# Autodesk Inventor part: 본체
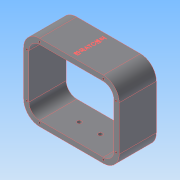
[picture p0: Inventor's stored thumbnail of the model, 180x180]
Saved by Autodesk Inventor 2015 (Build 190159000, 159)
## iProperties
Created: 2016-12
Part Number: 본체
Material: 알루미늄 6061
Document SubType Name: Modeling
Designer: mduedu
Density: 2.71 g/cm^3
Mass: 1066.02 g
Surface Area: 923.723 cm^2
Volume: 393.366 cm^3
Appearance: 기본값
Author: mduedu
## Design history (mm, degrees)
sketch "스케치1"
  geometry: L1 (-60, 72)-(60, 72); L2 (90, 42)-(90, -42); L3 (60, -72)-(-60, -72); L4 (-90, -42)-(-90, 42); A1 r 30 centre (-60, 42) between (-60, 72) and (-90, 42); A2 r 30 centre (60, 42) between (90, 42) and (60, 72); A3 r 30 centre (60, -42) between (60, -72) and (90, -42); A4 r 30 centre (-60, -42) between (-90, -42) and (-60, -72); 1 further point
  constraints: 8 end point, 8 point on circle, 8 tangent, 4 centre point, 3 equal radius, 2 parallel, 1 horizontal, 1 perpendicular
  dimensions: "d106" = 30 radius of A1; "d107" = 72 distance from line of L1 point (0, 0); "d108" = 144 distance between parallel lines of L3 L1; "d109" = 90 distance from line of L4 point (0, 0); "d110" = 180 distance between parallel lines of L2 L4
extrude "돌출1" new body sketch "스케치1" stored distance "d3" = 70; taper "d4" = 0 deg
feature "쉘1" dims "d5" = 10
sketch "스케치10"
  geometry: L1 (-30, 0)-(-30, 70) reference; 3 further points
  constraints: 2 coincident, 1 other
  dimensions: "d111" = 90 distance from line of point (60, 35) L1
feature "엠보싱1" sketch "스케치10" dims "d61" = 0.5, "d62" = 0, "d106" = 30, "d107" = 72, "d108" = 144, "d109" = 90, "d110" = 180
sketch "스케치16"
  geometry: L1 (-60, 62)-(60, 62) reference; L2 (80, 42)-(80, -42) reference; L3 (60, -62)-(-60, -62) reference; L4 (-80, -42)-(-80, 42) reference; L5 (60, 72)-(-60, 72) reference; L6 (-90, 42)-(-90, -42) reference; L7 (-60, -72)-(60, -72) reference; L8 (90, -42)-(90, 42) reference; L9 (60, 66)-(-60, 66); L10 (-84, 42)-(-84, -42); L11 (-60, -66)-(60, -66); L12 (84, -42)-(84, 42); A1 r 20 centre (60, 42) between (80, 42) and (60, 62) reference; A2 r 20 centre (60, -42) between (60, -62) and (80, -42) reference; A3 r 20 centre (-60, -42) between (-80, -42) and (-60, -62) reference; A4 r 20 centre (-60, 42) between (-60, 62) and (-80, 42) reference; A5 r 30 centre (-60, 42) between (-60, 72) and (-90, 42) reference; A6 r 30 centre (-60, -42) between (-90, -42) and (-60, -72) reference; A7 r 30 centre (60, -42) between (60, -72) and (90, -42) reference; A8 r 30 centre (60, 42) between (90, 42) and (60, 72) reference; A9 r 24 centre (-60, 42) between (-60, 66) and (-84, 42); A10 r 24 centre (-60, -42) between (-84, -42) and (-60, -66); A11 r 24 centre (60, -42) between (60, -66) and (84, -42); A12 r 24 centre (60, 42) between (84, 42) and (60, 66); 9 further points
  constraints: 8 coincident, 8 end point, 8 point on circle, 4 centre point, 7 other
  dimensions: "d124" = 6 distance between parallel lines of L9 L5
hole "구멍6" sketch "스케치16" at (-60, 66), (-84, 42), (-84, -42), (-60, -66), (60, -66), (84, -42), (84, 42), (60, 66) diameter "d113" = 3.242; stored, may be unused: countersink angle "d117" = 90 deg, drill point angle "d119" = 118 deg; dims "d114" = 7, "d115" = 4, "d116" = 2, "d118" = 9
sketch "스케치15"
  geometry: L1 (0, -70)-(0, 0) reference; L2 (-22.361, 0)-(0, 0) reference; L3 (-22.361, -70)-(-22.361, 0) reference; L4 (0, -70)-(-22.361, -70) reference; L5 (120, -70)-(0, -70) reference; L6 (120, -70)-(120, 0) reference; L7 (120, 0)-(142.361, 0) reference; L8 (142.361, 0)-(142.361, -70) reference; L9 (142.361, -70)-(120, -70) reference; L10 (0, 0)-(120, 0) reference; L11 (60, 0)-(60, -70); L12 (-22.361, -35)-(142.361, -35); C1 r 4 at (40, -35); C2 r 4 at (80, -35); 1 further point
  constraints: 4 end point, 4 midpoint, 2 centre point, 2 point on line, 1 equal radius
  dimensions: "d120" = 8 diameter of C1; "d122" = 20 distance from line of L11 C1.centre; "d123" = 40 distance of C2.centre C1.centre
extrude "돌출6" cut sketch "스케치15" stored distance "d94" = 10; taper "d95" = 0 deg
node "솔리드1"
mirror "대칭2"
node "투영된 루프5"
node "절단 모서리 투영2"
